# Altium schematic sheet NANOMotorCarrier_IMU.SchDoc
size A4
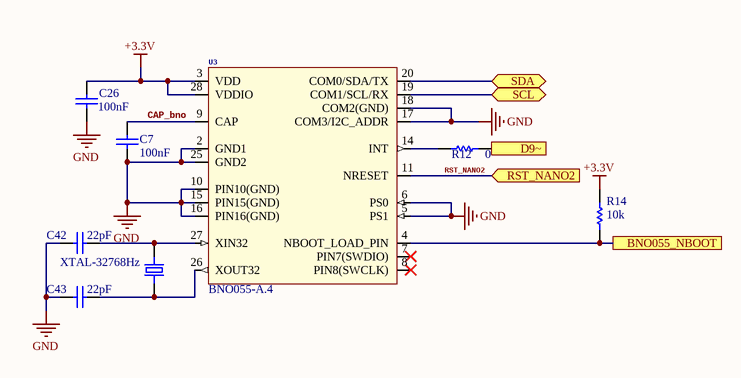
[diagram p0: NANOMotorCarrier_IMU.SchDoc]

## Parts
C7  value 100nF  [CAP-0402]  (hidden comment: GRM155R61H104KE19D)
C26  value 100nF  [CAP-0402]  (hidden comment: GRM155R61H104KE19D)
C42  value 22pF  [CAP-0402]  (hidden comment: C0402C220J5GAC7411)
C43  value 22pF  [CAP-0402]  (hidden comment: C0402C220J5GAC7411)
R12  value 0  [RES-0402]  (hidden comment: CRCW04020000Z0EDC)
R14  value 10k  [RES-0402]  (hidden comment: CRCW040210K0FKED)
U3  BNO055-A.4  [BNO055]
XTAL-32768Hz  Q13FC1350000400  [ABS07]  (value not drawn)

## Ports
BNO055_NBOOT, D9~, RST_NANO2 (in), SCL (bidir), SDA (bidir)

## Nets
+3.3V: C26.2 R14.1 U3.3(VDD) U3.28(VDDIO)
GND: C7.1 C26.1 C42.1 C43.1 U3.2(GND1) U3.5(PS1) U3.6(PS0) U3.10(PIN10(GND)) U3.15(PIN15(GND)) U3.16(PIN16(GND)) U3.17(COM3/I2C_ADDR) U3.18(COM2(GND)) U3.25(GND2)
BNO055_NBOOT: R14.2 U3.4(NBOOT_LOAD_PIN) ; port BNO055_NBOOT
CAP_bno: C7.2 U3.9(CAP)
D9~: R12.2 ; port D9~
RST_NANO2: U3.11(NRESET) ; port RST_NANO2
SCL: U3.19(COM1/SCL/RX) ; port SCL
SDA: U3.20(COM0/SDA/TX) ; port SDA
NetC42_2: C42.2 U3.27(XIN32) XTAL-32768Hz.2
NetC43_2: C43.2 U3.26(XOUT32) XTAL-32768Hz.1
NetR12_1: R12.1 U3.14(INT)

Not connected (* = marked no-connect by the designer): U3 7(PIN7(SWDIO))* 8(PIN8(SWCLK))*

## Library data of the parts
C7 C26 = C0015-A.3: CAP CHIP 0402 100nF 50V X5R 10%; Manufacturer: Murata; Code Arduino: A5141
C42 C43 = C0029-A.3: CAP CHIP 0402 22pF 50V C0G 5%; Manufacturer: KEMET; Code Arduino: 0137
R12 = R0000-A.3: RES CHIP 0402 0R 1/16W; Manufacturer: Vishay; Code Arduino: 0039; Power: 63mW; Tolerance: J
R14 = R0003-A.3: RES CHIP 0402 10K 1% 1/16W; Manufacturer: Vishay; Code Arduino: 0136; Power: 63mW
U3 = U0043-A.3: IC 3 axis Acc/Gyro/Mag from Bosch; Code Arduino: 1658; Device Type: SENSOR
XTAL-32768Hz = X0003-A.2: CRYSTAL SMD 32,768K3,2x1,5H,9RoHS; Manufacturer: Epson; Code Arduino: 0213; Series Resistance: 70kR; Frequency Tolerance: 20ppm; Load Capacitance: 12.5pF; Frequency: 32.768kHz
